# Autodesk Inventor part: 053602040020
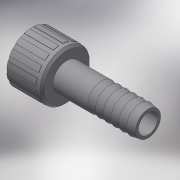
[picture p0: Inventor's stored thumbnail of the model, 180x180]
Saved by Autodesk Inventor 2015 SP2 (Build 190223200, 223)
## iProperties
Created: 2017-10
Part Number: 053602040020
Material: Generic
Description: PLASSON HOSE NOZZLE+NUT/THR. 2"-40
Document SubType Name: Modeling
Designer: KIM
Density: 1 g/cm^3
Appearance: Default
Author: KIM
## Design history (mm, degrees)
derived "053602.ipt"
feature "Solid1::053602.ipt"
tag "TaggingFeature1"
body "Solid1"
other parameters: "d0" = 97, "d1" = 170 deg, "d5" = 67.9872, "d6" = 28, "d8" = 38.8, "d9" = 56.656, "d10" = 29.1, "d11" = 17.46, "d12" = 24.25, "d13" = 66.85408, "d14" = 2.8328, "d17" = 5.6656, "d18" = 2.8328, "d19" = 27.16, "d20" = 0, "d22" = 360 deg, "d_" = 16, "H_" = 97, "G_" = 56.656
